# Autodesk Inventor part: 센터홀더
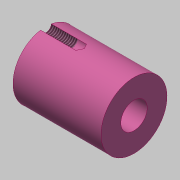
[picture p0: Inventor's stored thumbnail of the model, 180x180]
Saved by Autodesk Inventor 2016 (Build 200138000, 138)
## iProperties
Created: 2019-10
Part Number: 센터홀더
Material: 강철, 연강
Document SubType Name: Modeling
Designer: mduedu
Density: 1 g/cm^3
Appearance: 분홍색
Author: mduedu
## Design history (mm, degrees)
sketch "스케치1"
  geometry: L1 (0, 0)-(20, 0); L2 (12, -3)-(20, -3); L3 (20, -3)-(20, -7.5); L4 (20, -7.5)-(0, -7.5); L5 (0, -7.5)-(0, -4.127); L6 (0, -4.127)-(12, -3.751); L7 (12, -3.751)-(12, -3)
  constraints: 14 end point, 2 horizontal, 2 parallel, 2 perpendicular, 2 vertical alignment
  dimensions: "d0" = 20 distance of L1.start L1.end; "d1" = 6 diameter of L2 L1; "d2" = 12 distance between parallel lines of L5 L7; "d3" = 7.502 diameter of L6.end L1; "d4" = 8.254 diameter of L5.end L1; "d5" = 15 diameter of L4 L1
revolve "회전1" sketch "스케치1" stored, may be unused: angle "d6" = 90 deg
sketch "스케치2"
  geometry: 3 further points
  constraints: 2 vertical alignment, 1 other
hole "구멍1" sketch "스케치2" at (0, 7.5) diameter "d7" = 2.459; stored, may be unused: countersink angle "d11" = 90 deg, drill point angle "d13" = 118 deg; dims "d8" = 6, "d9" = 4, "d10" = 2, "d12" = 8
node "솔리드1"
